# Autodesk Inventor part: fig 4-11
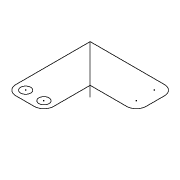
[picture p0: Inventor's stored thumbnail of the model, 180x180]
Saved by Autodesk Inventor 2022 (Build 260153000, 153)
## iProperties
Created: 2005-02
Part Number: fig 4-11
Document SubType Name: Modeling
Designer: CADCIM
Manufacturer: Standard
Standards Organization: Custom
Density: 1 g/cm^3
Material: Generic
Appearance: Default
Author: CADCIM
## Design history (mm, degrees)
sketch "Sketch1"
  geometry: L1 (5.141, 24.979)-(-32.827, 24.979); L2 (-32.827, 24.979)-(-32.827, -12.989); L3 (-27.827, -17.989)-(-18.492, -17.989); L4 (-13.492, -12.989)-(-13.492, 5.644); L5 (-13.492, 5.644)-(5.141, 5.644); L6 (10.141, 10.644)-(10.141, 19.979); L7 (-32.827, 24.979)-(-8.203, 0.354); C1 r 2.58 at (-27.827, -12.989); C2 r 2.58 at (-18.492, -12.989); A1 r 5 centre (-27.827, -12.989) between (-32.827, -12.989) and (-27.827, -17.989); A2 r 5 centre (-18.492, -12.989) between (-18.492, -17.989) and (-13.492, -12.989); A3 r 5 centre (5.141, 10.644) between (5.141, 5.644) and (10.141, 10.644); A4 r 5 centre (5.141, 19.979) between (10.141, 19.979) and (5.141, 24.979)
  constraints: 14 end point, 8 point on circle, 8 tangent, 6 centre point, 4 equal radius, 4 parallel, 3 perpendicular, 2 coincident, 1 horizontal, 1 point on line
